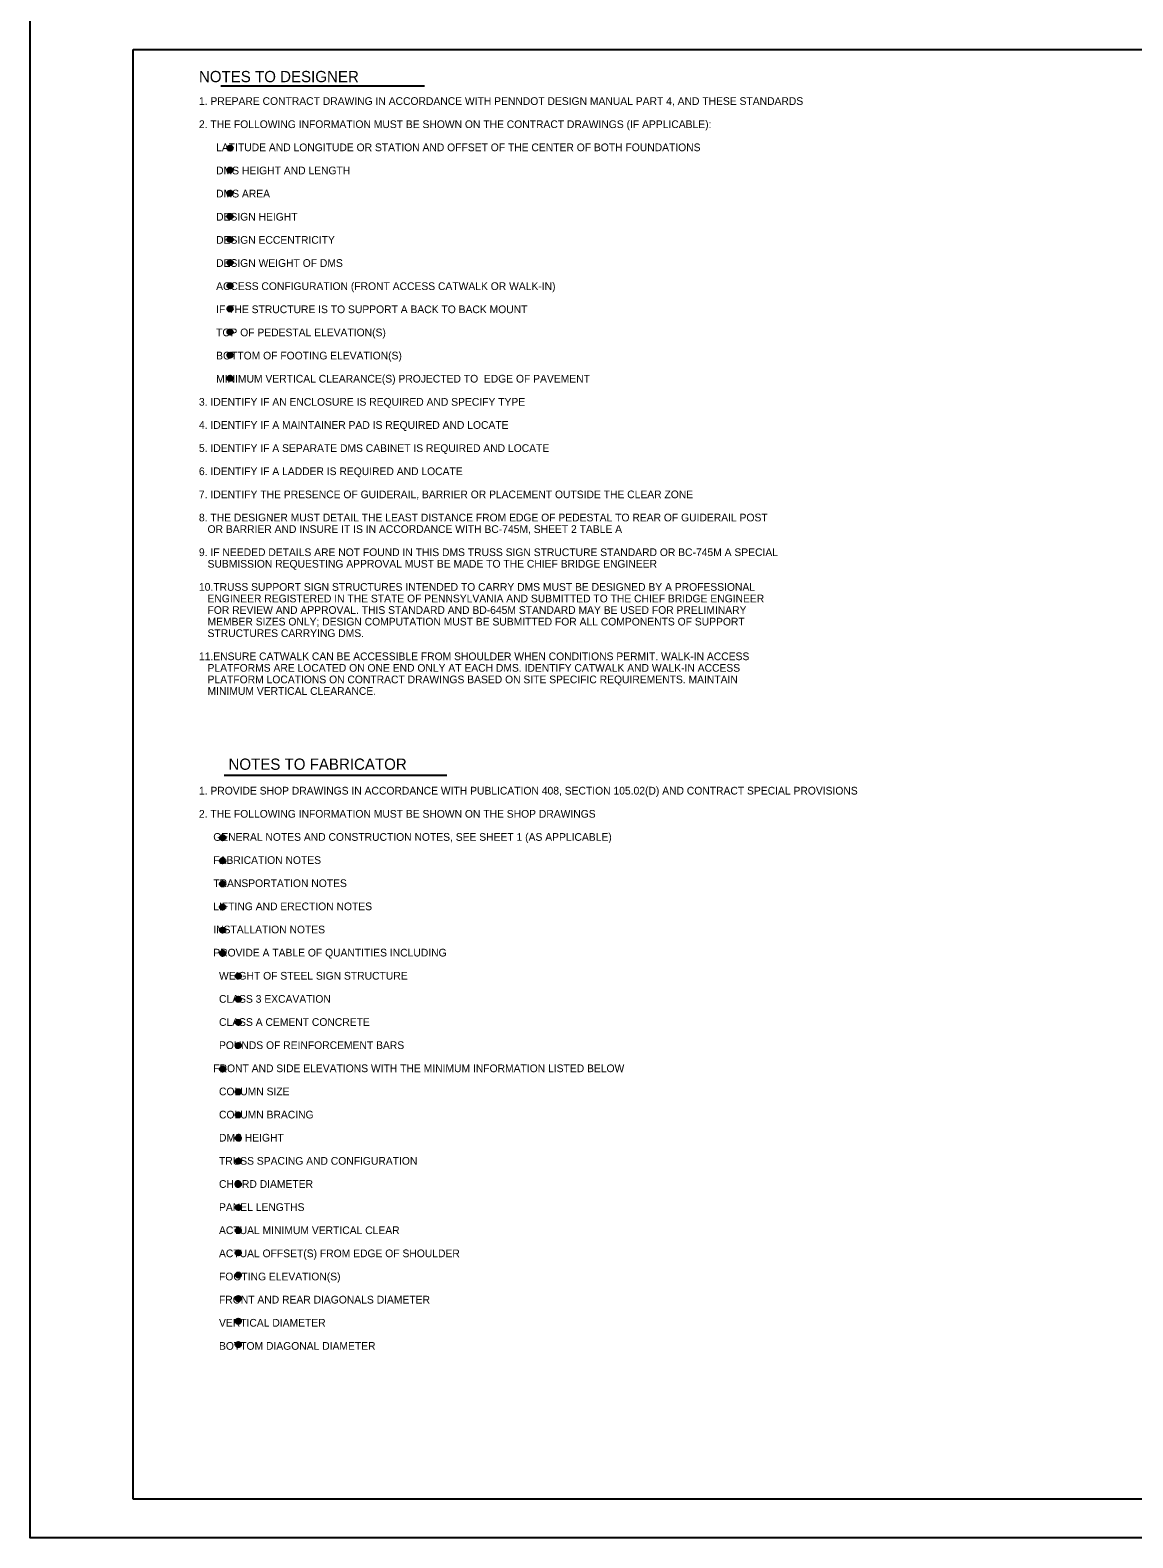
# Model space of a CAD drawing. Extents: x 3831399 to 3833095, y 499014 to 500202.
# Drawn here: x 3831399 to 3831828, y 499014 to 499601 of the extents above; entities that cross this region are included whole.
import ezdxf

# ---------------------------------------------------------------- set-up
doc = ezdxf.new("R2010")
doc.units = 0
for name, color, linetype in [('2', 7, 'Continuous'), ('DIM TXT', 7, 'Continuous'), ('PLT-BNDY', 7, 'Continuous'), ('Pr_dimension_ln', 7, 'Continuous')]:
    doc.layers.add(name, color=color, linetype=linetype)

msp = doc.modelspace()

# ---------------------------------------------------------------- linework, layer by layer
at = {"layer": '2'}
for p, q in [((3831439.16, 499029.03), (3831439.16, 499593.03)), ((3831439.16, 499593.03), (3832225.16, 499593.03)), ((3832225.16, 499029.03), (3831439.16, 499029.03))]:
    msp.add_line(p, q, dxfattribs=at)
at = {"layer": 'DIM TXT'}
for centre, radius in [((3831476.86, 499554.63), 1.04), ((3831476.86, 499554.63), 0.783), ((3831476.86, 499554.63), 0.522), ((3831476.86, 499554.63), 0.261), ((3831476.86, 499554.63), 0.00000209), ((3831476.86, 499546.1), 1.04), ((3831476.86, 499546.1), 0.783), ((3831476.86, 499546.1), 0.522), ((3831476.86, 499546.1), 0.261), ((3831476.86, 499546.1), 0.00000209), ((3831476.86, 499537.1), 1.04), ((3831476.86, 499537.1), 0.783), ((3831476.86, 499537.1), 0.522), ((3831476.86, 499537.1), 0.261), ((3831476.86, 499537.1), 0.00000209), ((3831476.86, 499528.1), 1.04), ((3831476.86, 499528.1), 0.783), ((3831476.86, 499528.1), 0.522), ((3831476.86, 499528.1), 0.261), ((3831476.86, 499528.1), 0.00000209), ((3831476.86, 499519.1), 1.04), ((3831476.86, 499519.1), 0.783), ((3831476.86, 499519.1), 0.522), ((3831476.86, 499519.1), 0.261), ((3831476.86, 499519.1), 0.00000209), ((3831476.86, 499510.1), 1.04), ((3831476.86, 499510.1), 0.783), ((3831476.86, 499510.1), 0.522), ((3831476.86, 499510.1), 0.261), ((3831476.86, 499510.1), 0.00000209), ((3831476.86, 499501.1), 1.04), ((3831476.86, 499501.1), 0.783), ((3831476.86, 499501.1), 0.522), ((3831476.86, 499501.1), 0.261), ((3831476.86, 499501.1), 0.00000209), ((3831476.86, 499492.1), 1.04), ((3831476.86, 499492.1), 0.783), ((3831476.86, 499492.1), 0.522), ((3831476.86, 499492.1), 0.261), ((3831476.86, 499492.1), 0.00000209), ((3831476.86, 499483.1), 1.04), ((3831476.86, 499483.1), 0.783), ((3831476.86, 499483.1), 0.522), ((3831476.86, 499483.1), 0.261), ((3831476.86, 499483.1), 0.00000209), ((3831476.86, 499474.1), 1.04), ((3831476.86, 499474.1), 0.783), ((3831476.86, 499474.1), 0.522), ((3831476.86, 499474.1), 0.261), ((3831476.86, 499474.1), 0.00000209), ((3831476.86, 499465.1), 1.04), ((3831476.86, 499465.1), 0.783), ((3831476.86, 499465.1), 0.522), ((3831476.86, 499465.1), 0.261), ((3831476.86, 499465.1), 0.00000209), ((3831474, 499286.4), 1.04), ((3831474, 499286.4), 0.783), ((3831474, 499286.4), 0.522), ((3831474, 499286.4), 0.261), ((3831474, 499286.4), 0.00000209), ((3831474, 499277.41), 1.04), ((3831474, 499277.41), 0.783), ((3831474, 499277.41), 0.522), ((3831474, 499277.41), 0.261), ((3831474, 499277.41), 0.00000209), ((3831474, 499268.41), 1.04), ((3831474, 499268.41), 0.783), ((3831474, 499268.41), 0.522), ((3831474, 499268.41), 0.261), ((3831474, 499268.41), 0.00000209), ((3831474, 499259.41), 1.04), ((3831474, 499259.41), 0.783), ((3831474, 499259.41), 0.522), ((3831474, 499259.41), 0.261), ((3831474, 499259.41), 0.00000209), ((3831474, 499250.41), 1.04), ((3831474, 499250.41), 0.783), ((3831474, 499250.41), 0.522), ((3831474, 499250.41), 0.261), ((3831474, 499250.41), 0.00000209), ((3831474, 499241.41), 1.04), ((3831474, 499241.41), 0.783), ((3831474, 499241.41), 0.522), ((3831474, 499241.41), 0.261), ((3831474, 499241.41), 0.00000209), ((3831480.08, 499232.55), 1.04), ((3831480.08, 499232.55), 0.783), ((3831480.08, 499232.55), 0.522), ((3831480.08, 499232.55), 0.261), ((3831480.08, 499232.55), 0.00000209), ((3831480.08, 499223.55), 1.04), ((3831480.08, 499223.55), 0.783), ((3831480.08, 499223.55), 0.522), ((3831480.08, 499223.55), 0.261), ((3831480.08, 499223.55), 0.00000209), ((3831480.08, 499214.55), 1.04), ((3831480.08, 499214.55), 0.783), ((3831480.08, 499214.55), 0.522), ((3831480.08, 499214.55), 0.261), ((3831480.08, 499214.55), 0.00000209), ((3831480.08, 499205.55), 1.04), ((3831480.08, 499205.55), 0.783), ((3831480.08, 499205.55), 0.522), ((3831480.08, 499205.55), 0.261), ((3831480.08, 499205.55), 0.00000209), ((3831474, 499196.41), 1.04), ((3831474, 499196.41), 0.783), ((3831474, 499196.41), 0.522), ((3831474, 499196.41), 0.261), ((3831474, 499196.41), 0.00000209), ((3831480.08, 499187.55), 1.04), ((3831480.08, 499187.55), 0.783), ((3831480.08, 499187.55), 0.522), ((3831480.08, 499187.55), 0.261), ((3831480.08, 499187.55), 0.00000209), ((3831480.08, 499178.55), 1.04), ((3831480.08, 499178.55), 0.783), ((3831480.08, 499178.55), 0.522), ((3831480.08, 499178.55), 0.261), ((3831480.08, 499178.55), 0.00000209), ((3831480.08, 499169.55), 1.04), ((3831480.08, 499169.55), 0.783), ((3831480.08, 499169.55), 0.522), ((3831480.08, 499169.55), 0.261), ((3831480.08, 499169.55), 0.00000209), ((3831480.08, 499160.55), 1.04), ((3831480.08, 499160.55), 0.783), ((3831480.08, 499160.55), 0.522), ((3831480.08, 499160.55), 0.261), ((3831480.08, 499160.55), 0.00000209), ((3831480.08, 499151.55), 1.04), ((3831480.08, 499151.55), 0.783), ((3831480.08, 499151.55), 0.522), ((3831480.08, 499151.55), 0.261), ((3831480.08, 499151.55), 0.00000209), ((3831480.08, 499142.55), 1.04), ((3831480.08, 499142.55), 0.783), ((3831480.08, 499142.55), 0.522), ((3831480.08, 499142.55), 0.261), ((3831480.08, 499142.55), 0.00000209), ((3831480.08, 499133.55), 1.04), ((3831480.08, 499133.55), 0.783), ((3831480.08, 499133.55), 0.522), ((3831480.08, 499133.55), 0.261), ((3831480.08, 499133.55), 0.00000209), ((3831480.08, 499124.89), 1.04), ((3831480.08, 499124.89), 0.783), ((3831480.08, 499124.89), 0.522), ((3831480.08, 499124.89), 0.261), ((3831480.08, 499124.89), 0.00000209), ((3831480.08, 499116.26), 1.04), ((3831480.08, 499116.26), 0.783), ((3831480.08, 499116.26), 0.522), ((3831480.08, 499116.26), 0.261), ((3831480.08, 499116.26), 0.00000209), ((3831480.08, 499107.12), 1.04), ((3831480.08, 499107.12), 0.783), ((3831480.08, 499107.12), 0.522), ((3831480.08, 499107.12), 0.261), ((3831480.08, 499107.12), 0.00000209), ((3831480.08, 499098.3), 1.04), ((3831480.08, 499098.3), 0.783), ((3831480.08, 499098.3), 0.522), ((3831480.08, 499098.3), 0.261), ((3831480.08, 499098.3), 0.00000209), ((3831480.08, 499089.19), 1.04), ((3831480.08, 499089.19), 0.783), ((3831480.08, 499089.19), 0.522), ((3831480.08, 499089.19), 0.261), ((3831480.08, 499089.19), 0.00000209)]:
    msp.add_circle(centre, radius, dxfattribs=at)
at = {"layer": 'PLT-BNDY'}
msp.add_lwpolyline([(3831399.16, 499608.03), (3832240.16, 499608.03), (3832240.16, 499014.03), (3831399.16, 499014.03)], close=True, dxfattribs=at)
at = {"layer": 'Pr_dimension_ln'}
for p, q in [((3831473.25, 499578.9), (3831552.53, 499578.9)), ((3831474.58, 499310.74), (3831561.22, 499310.74))]:
    msp.add_line(p, q, dxfattribs=at)

# ---------------------------------------------------------------- texts
for s, height, p in [('    NOTES TO DESIGNER', 4.3799, (3831458.27, 499580.29)), ('1. PREPARE CONTRACT DRAWING IN ACCORDANCE WITH PENNDOT DESIGN MANUAL PART 4, AND THESE STANDARDS', 2.9999, (3831464.78, 499571.44)), ('2. THE FOLLOWING INFORMATION MUST BE SHOWN ON THE CONTRACT DRAWINGS (IF APPLICABLE):', 2.9999, (3831464.78, 499562.44)), ('      LATITUDE AND LONGITUDE OR STATION AND OFFSET OF THE CENTER OF BOTH FOUNDATIONS', 2.9999, (3831464.78, 499553.44)), ('      DMS HEIGHT AND LENGTH', 2.9999, (3831464.78, 499544.44)), ('      DMS AREA', 2.9999, (3831464.78, 499535.44)), ('      DESIGN HEIGHT', 2.9999, (3831464.78, 499526.44)), ('      DESIGN ECCENTRICITY', 2.9999, (3831464.78, 499517.44)), ('      DESIGN WEIGHT OF DMS', 2.9999, (3831464.78, 499508.44)), ('      ACCESS CONFIGURATION (FRONT ACCESS CATWALK OR WALK-IN)', 2.9999, (3831464.78, 499499.44)), ('      IF THE STRUCTURE IS TO SUPPORT A BACK TO BACK MOUNT', 2.9999, (3831464.78, 499490.44)), ('      TOP OF PEDESTAL ELEVATION(S)', 2.9999, (3831464.78, 499481.44)), ('      BOTTOM OF FOOTING ELEVATION(S)', 2.9999, (3831464.78, 499472.44)), ('      MINIMUM VERTICAL CLEARANCE(S) PROJECTED TO  EDGE OF PAVEMENT', 2.9999, (3831464.78, 499463.44)), ('3. IDENTIFY IF AN ENCLOSURE IS REQUIRED AND SPECIFY TYPE', 2.9999, (3831464.78, 499454.44)), ('4. IDENTIFY IF A MAINTAINER PAD IS REQUIRED AND LOCATE', 2.9999, (3831464.78, 499445.44)), ('5. IDENTIFY IF A SEPARATE DMS CABINET IS REQUIRED AND LOCATE', 2.9999, (3831464.78, 499436.44)), ('6. IDENTIFY IF A LADDER IS REQUIRED AND LOCATE', 2.9999, (3831464.78, 499427.44)), ('7. IDENTIFY THE PRESENCE OF GUIDERAIL, BARRIER OR PLACEMENT OUTSIDE THE CLEAR ZONE', 2.9999, (3831464.78, 499418.44)), ('8. THE DESIGNER MUST DETAIL THE LEAST DISTANCE FROM EDGE OF PEDESTAL TO REAR OF GUIDERAIL POST', 2.9999, (3831464.78, 499409.44)), ('   OR BARRIER AND INSURE IT IS IN ACCORDANCE WITH BC-745M, SHEET 2 TABLE A', 2.9999, (3831464.78, 499404.94)), ('9. IF NEEDED DETAILS ARE NOT FOUND IN THIS DMS TRUSS SIGN STRUCTURE STANDARD OR BC-745M A SPECIAL', 2.9999, (3831464.78, 499395.94)), ('   SUBMISSION REQUESTING APPROVAL MUST BE MADE TO THE CHIEF BRIDGE ENGINEER', 2.9999, (3831464.78, 499391.44)), ('10.TRUSS SUPPORT SIGN STRUCTURES INTENDED TO CARRY DMS MUST BE DESIGNED BY A PROFESSIONAL ', 2.9999, (3831464.78, 499382.44)), ('   ENGINEER REGISTERED IN THE STATE OF PENNSYLVANIA AND SUBMITTED TO THE CHIEF BRIDGE ENGINEER ', 2.9999, (3831464.78, 499377.94)), ('   FOR REVIEW AND APPROVAL. THIS STANDARD AND BD-645M STANDARD MAY BE USED FOR PRELIMINARY ', 2.9999, (3831464.78, 499373.45)), ('   MEMBER SIZES ONLY; DESIGN COMPUTATION MUST BE SUBMITTED FOR ALL COMPONENTS OF SUPPORT', 2.9999, (3831464.78, 499368.95)), ('   STRUCTURES CARRYING DMS.', 2.9999, (3831464.78, 499364.45)), ('11.ENSURE CATWALK CAN BE ACCESSIBLE FROM SHOULDER WHEN CONDITIONS PERMIT. WALK-IN ACCESS', 2.9999, (3831464.78, 499355.45)), ('   PLATFORMS ARE LOCATED ON ONE END ONLY AT EACH DMS. IDENTIFY CATWALK AND WALK-IN ACCESS', 2.9999, (3831464.78, 499350.95)), ('   PLATFORM LOCATIONS ON CONTRACT DRAWINGS BASED ON SITE SPECIFIC REQUIREMENTS. MAINTAIN', 2.9999, (3831464.78, 499346.45)), ('   MINIMUM VERTICAL CLEARANCE.    ', 2.9999, (3831464.78, 499341.95)), ('NOTES TO FABRICATOR', 4.3799, (3831476.26, 499312.8)), ('1. PROVIDE SHOP DRAWINGS IN ACCORDANCE WITH PUBLICATION 408, SECTION 105.02(D) AND CONTRACT SPECIAL PROVISIONS', 2.99992, (3831464.78, 499303.18)), ('2. THE FOLLOWING INFORMATION MUST BE SHOWN ON THE SHOP DRAWINGS', 2.9999, (3831464.78, 499294.18)), ('     GENERAL NOTES AND CONSTRUCTION NOTES, SEE SHEET 1 (AS APPLICABLE)', 2.9999, (3831464.78, 499285.18)), ('     FABRICATION NOTES', 2.9999, (3831464.78, 499276.18)), ('     TRANSPORTATION NOTES', 2.9999, (3831464.78, 499267.18)), ('     LIFTING AND ERECTION NOTES', 2.9999, (3831464.78, 499258.18)), ('     INSTALLATION NOTES', 2.9999, (3831464.78, 499249.18)), ('     PROVIDE A TABLE OF QUANTITIES INCLUDING', 2.9999, (3831464.78, 499240.18)), ('       WEIGHT OF STEEL SIGN STRUCTURE', 2.9999, (3831464.78, 499231.18)), ('       CLASS 3 EXCAVATION', 2.9999, (3831464.78, 499222.18)), ('       CLASS A CEMENT CONCRETE', 2.9999, (3831464.78, 499213.18)), ('       POUNDS OF REINFORCEMENT BARS', 2.9999, (3831464.78, 499204.18)), ('     FRONT AND SIDE ELEVATIONS WITH THE MINIMUM INFORMATION LISTED BELOW', 2.9999, (3831464.78, 499195.18)), ('       COLUMN SIZE', 2.9999, (3831464.78, 499186.18)), ('       COLUMN BRACING', 2.9999, (3831464.78, 499177.18)), ('       DMS HEIGHT', 2.9999, (3831464.78, 499168.18)), ('       TRUSS SPACING AND CONFIGURATION', 2.9999, (3831464.78, 499159.18)), ('       CHORD DIAMETER', 2.9999, (3831464.78, 499150.18)), ('       PANEL LENGTHS', 2.9999, (3831464.78, 499141.19)), ('       ACTUAL MINIMUM VERTICAL CLEAR', 2.9999, (3831464.78, 499132.19)), ('       ACTUAL OFFSET(S) FROM EDGE OF SHOULDER', 2.9999, (3831464.78, 499123.19)), ('       FOOTING ELEVATION(S)', 2.9999, (3831464.78, 499114.19)), ('       FRONT AND REAR DIAGONALS DIAMETER', 2.9999, (3831464.78, 499105.19)), ('       VERTICAL DIAMETER', 2.9999, (3831464.78, 499096.19)), ('       BOTTOM DIAGONAL DIAMETER', 2.9999, (3831464.78, 499087.19))]:
    msp.add_text(s, height=height, rotation=360, dxfattribs=at).set_placement(p)

doc.saveas('drawing.dxf')
